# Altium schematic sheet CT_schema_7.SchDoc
size 277 x 170 mm
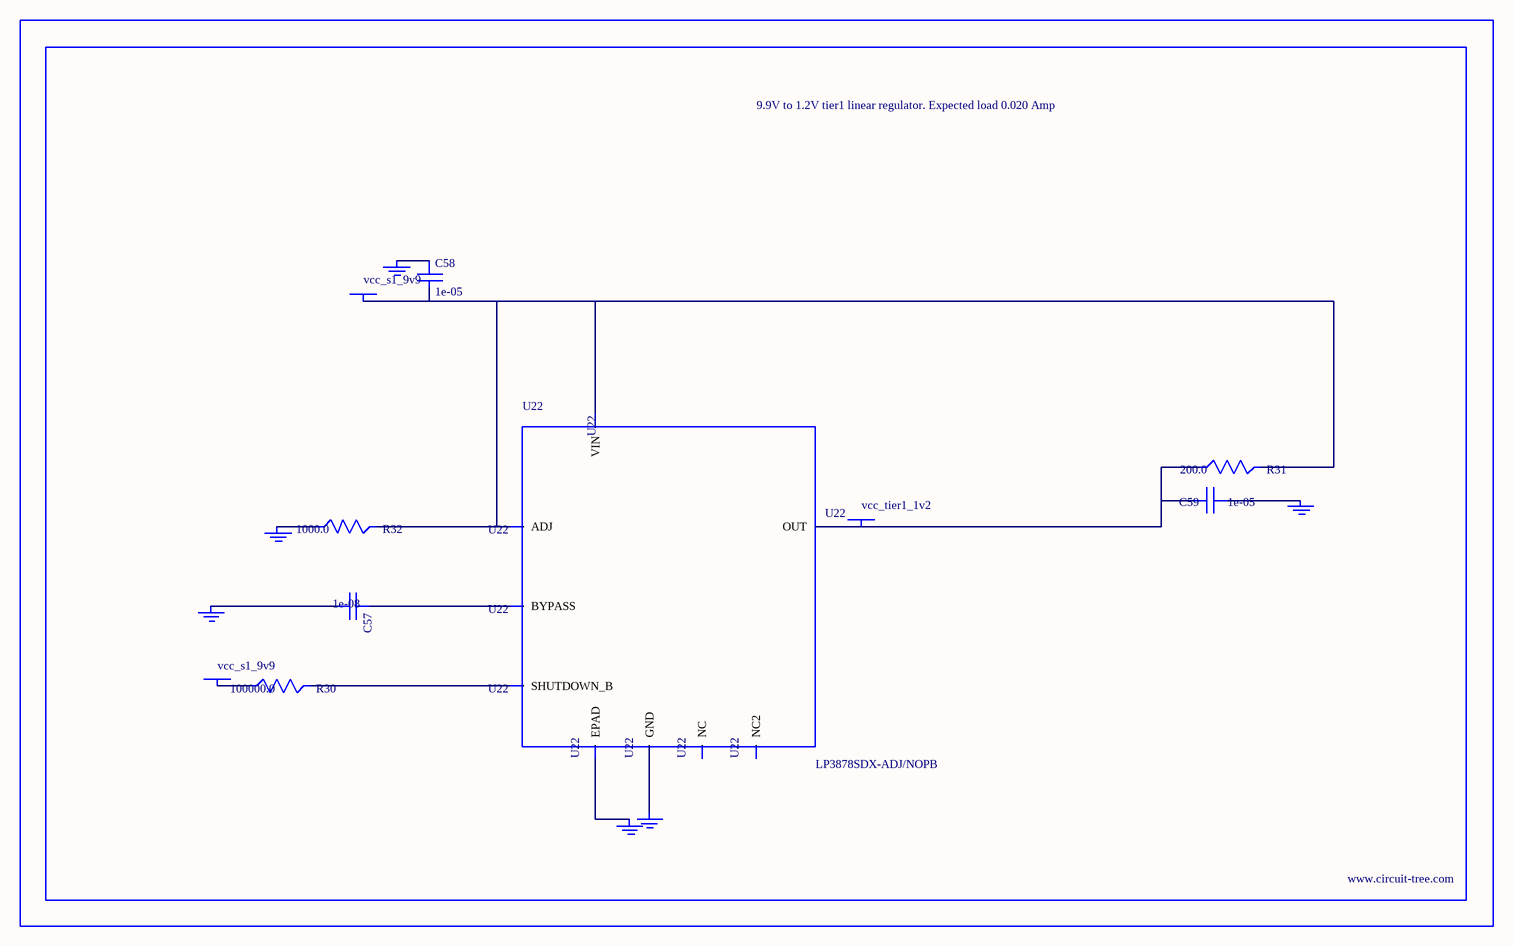
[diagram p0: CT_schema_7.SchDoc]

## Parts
BORDER6  (no value)
C57  1e-08  [C0402]
C58  1e-05  [C1206]
C59  1e-05  [C0805]
GND_INSTANCE_6_0  (no value)
GND_INSTANCE_6_1  (no value)
GND_INSTANCE_6_2  (no value)
GND_INSTANCE_6_3  (no value)
GND_INSTANCE_6_4  (no value)
GND_INSTANCE_6_5  (no value)
POWER_INSTANCE_6_0  vcc_s1_9v9
POWER_INSTANCE_6_1  vcc_s1_9v9
POWER_INSTANCE_6_2  vcc_tier1_1v2
R30  100000.0  [R0603]
R31  200.0  [R0603]
R32  1000.0  [R0603]
U22  LP3878SDX-ADJ/NOPB  [WSON-8]

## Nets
NetC57_1: C57.1 U22.1(BYPASS)
NetC57_2: C57.2 GND_INSTANCE_6_0.0(GND)
NetC58_1: C58.1 GND_INSTANCE_6_1.0(GND)
NetC58_2: C58.2 POWER_INSTANCE_6_0.0(PWR) R31.2 R32.2 U22.4(VIN) U22.6(ADJ)
NetC59_1: C59.1 GND_INSTANCE_6_2.0(GND)
NetC59_2: C59.2 POWER_INSTANCE_6_2.0(PWR) R31.1 U22.5(OUT)
NetGND_INSTANCE_6_3_0: GND_INSTANCE_6_3.0(GND) R32.1
NetGND_INSTANCE_6_4_0: GND_INSTANCE_6_4.0(GND) U22.PAD(EPAD)
NetGND_INSTANCE_6_5_0: GND_INSTANCE_6_5.0(GND) U22.3(GND)
NetPOWER_INSTANCE_6_1_0: POWER_INSTANCE_6_1.0(PWR) R30.1
NetR30_2: R30.2 U22.8(SHUTDOWN_B)

Not connected (* = marked no-connect by the designer): U22 2(NC) 7(NC2)

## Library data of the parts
BORDER6 = BORDER_PAGE6
C57 = C0402C103K3RAC
C58 = C1206C106K3RACTU
C59 = GRM219R60J106ME19D
GND_INSTANCE_6_0-GND_INSTANCE_6_5 = GND
POWER_INSTANCE_6_0-POWER_INSTANCE_6_2 = PWR
R30 = RC0603JR-07100KL
R31 = RC0603JR-07200RL
R32 = RC0603JR-071KL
